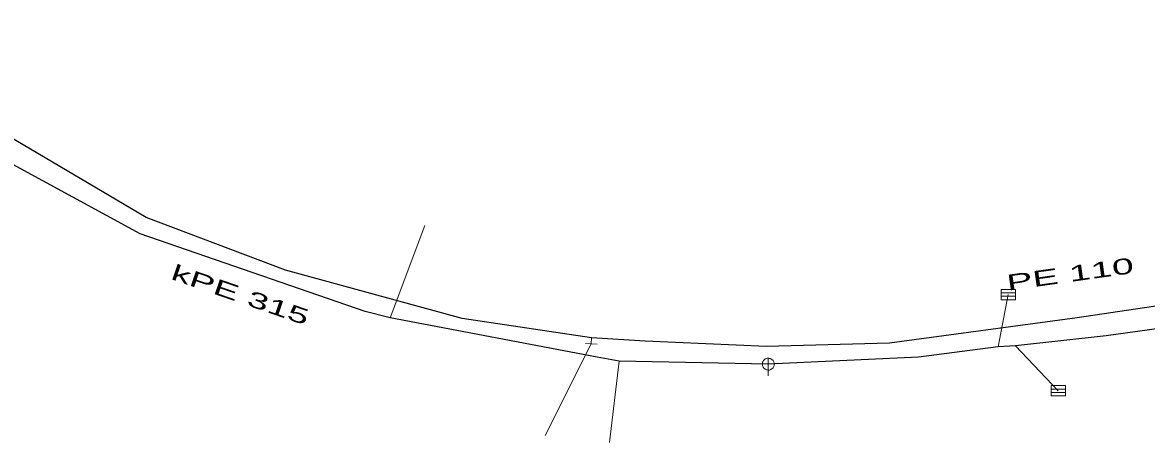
# Model space of a CAD drawing. Extents: x -687468 to -685917, y -974192 to -973456.
# Drawn here: x -686388.17 to -686340.71, y -973695.83 to -973678.09 of the extents above; entities that cross this region are included whole.
import ezdxf
from ezdxf.enums import TextEntityAlignment as Align

# ---------------------------------------------------------------- set-up
doc = ezdxf.new("R2010")
doc.units = 0
doc.header["$LTSCALE"] = 0.27
for name, color, linetype, lineweight in [('1', 7, 'Continuous', 13), ('11', 7, 'Continuous', 13), ('13', 7, 'Continuous', 13), ('14', 7, 'Continuous', 25), ('17', 7, 'Continuous', 25), ('22', 7, 'Continuous', 13), ('34', 7, 'Continuous', 13)]:
    doc.layers.add(name, color=color, linetype=linetype, lineweight=lineweight)

msp = doc.modelspace()

# ---------------------------------------------------------------- linework, layer by layer
at = {"layer": '11'}
for p, q in [((-686371.18, -973686.67), (-686372.649, -973690.57)), ((-686346.55, -973689.579), (-686346.971, -973691.789)), ((-686344.44, -973693.64), (-686346.239, -973691.745)), ((-686363.39, -973695.829), (-686362.98, -973692.39))]:
    msp.add_line(p, q, dxfattribs=at)
at = {"layer": '13'}
msp.add_line((-686364.155, -973691.659), (-686366.1, -973695.53), dxfattribs=at)
at = {"layer": '14', "lineweight": 13}
msp.add_line((-686364.155, -973691.659), (-686364.14, -973691.41), dxfattribs=at)
at = {"layer": '14'}
for points in [[(-686356.68, -973692.52), (-686362.98, -973692.39), (-686363.91, -973692.219), (-686372.649, -973690.57), (-686373.699, -973690.289), (-686383.199, -973687.01), (-686390.16, -973683.23), (-686393.66, -973681.449), (-686402, -973678.71)], [(-686308.71, -973691.92), (-686313.611, -973691.059), (-686316.129, -973690.57), (-686318.89, -973690.16), (-686323.84, -973689.829), (-686331.949, -973689.879), (-686342.41, -973691.32), (-686346.239, -973691.745), (-686346.971, -973691.789), (-686350.34, -973692.219), (-686356.68, -973692.52)]]:
    msp.add_lwpolyline(points, dxfattribs=at)
at = {"layer": '17'}
msp.add_lwpolyline([(-686335.77, -973689.399), (-686343.64, -973690.559), (-686351.559, -973691.629), (-686356.76, -973691.77), (-686361.879, -973691.55), (-686364.14, -973691.41), (-686369.609, -973690.59), (-686377.059, -973688.55), (-686382.949, -973686.329), (-686388.76, -973682.89), (-686393.69, -973680.43), (-686400.129, -973678.44), (-686402.12, -973678.09), (-686403.64, -973678.93), (-686407.599, -973681.789)], dxfattribs=at)
at = {"layer": '22'}
for p, q in [((-686346.845, -973689.508), (-686346.247, -973689.508)), ((-686346.845, -973689.654), (-686346.247, -973689.654)), ((-686356.679, -973692.268), (-686356.68, -973693.012)), ((-686344.735, -973693.569), (-686344.137, -973693.569)), ((-686344.735, -973693.715), (-686344.137, -973693.715))]:
    msp.add_line(p, q, dxfattribs=at)
for points in [[(-686346.845, -973689.362), (-686346.247, -973689.362), (-686346.247, -973689.799), (-686346.845, -973689.799)], [(-686356.428, -973692.52), (-686356.429, -973692.494), (-686356.433, -973692.468), (-686356.439, -973692.442), (-686356.449, -973692.418), (-686356.461, -973692.394), (-686356.475, -973692.372), (-686356.492, -973692.351), (-686356.51, -973692.333), (-686356.531, -973692.316), (-686356.553, -973692.302), (-686356.577, -973692.29), (-686356.601, -973692.28), (-686356.627, -973692.274), (-686356.653, -973692.27), (-686356.679, -973692.268), (-686356.705, -973692.269), (-686356.731, -973692.273), (-686356.757, -973692.279), (-686356.782, -973692.289), (-686356.805, -973692.301), (-686356.827, -973692.315), (-686356.848, -973692.332), (-686356.866, -973692.35), (-686356.883, -973692.371), (-686356.897, -973692.393), (-686356.909, -973692.417), (-686356.919, -973692.441), (-686356.926, -973692.467), (-686356.93, -973692.493), (-686356.932, -973692.519), (-686356.931, -973692.545), (-686356.927, -973692.571), (-686356.92, -973692.597), (-686356.91, -973692.622), (-686356.898, -973692.645), (-686356.884, -973692.667), (-686356.867, -973692.688), (-686356.849, -973692.706), (-686356.828, -973692.723), (-686356.806, -973692.737), (-686356.783, -973692.749), (-686356.758, -973692.759), (-686356.732, -973692.766), (-686356.706, -973692.77), (-686356.68, -973692.772), (-686356.654, -973692.771), (-686356.628, -973692.767), (-686356.602, -973692.76), (-686356.578, -973692.75), (-686356.554, -973692.738), (-686356.532, -973692.724), (-686356.511, -973692.707), (-686356.493, -973692.689), (-686356.476, -973692.668), (-686356.462, -973692.646), (-686356.45, -973692.623), (-686356.44, -973692.598), (-686356.434, -973692.572), (-686356.43, -973692.546)], [(-686344.735, -973693.423), (-686344.137, -973693.423), (-686344.137, -973693.86), (-686344.735, -973693.86)]]:
    msp.add_lwpolyline(points, close=True, dxfattribs=at)
at = {"layer": '34'}
msp.add_line((-686363.907, -973691.673), (-686364.402, -973691.644), dxfattribs=at)

# ---------------------------------------------------------------- texts
at = {"layer": '1'}
for s, rotation, width, p in [('PE 110', 8, 1.85, (-686343.891, -973689.043)), ('kPE 315 ', 341, 1.8, (-686378.867, -973689.974))]:
    msp.add_text(s, height=0.6667, rotation=rotation, dxfattribs=dict(at, width=width)).set_placement(p, align=Align.CENTER)

doc.saveas('drawing.dxf')
